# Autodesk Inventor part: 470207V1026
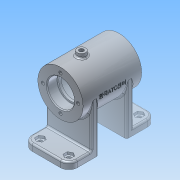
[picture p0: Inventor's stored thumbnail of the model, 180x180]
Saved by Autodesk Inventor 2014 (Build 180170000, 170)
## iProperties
Created: 2017-02
Part Number: 470207V1026
Material: 알루미늄 6061
Document SubType Name: Modeling
Designer: NET
Density: 2.71 g/cm^3
Appearance: 알루미늄 - 평지
Mass: 354.897 g
Surface Area: 425.393 cm^2
Volume: 130.958 cm^3
Author: NET
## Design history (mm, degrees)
sketch "스케치1"
  geometry: L1 (0, 0)-(70, 0); L2 (70, 27)-(70, 17); L3 (0, 17)-(0, 27); L4 (0, 27)-(70, 27); L5 (69, 16)-(58.3, 16); L6 (58, 15.7)-(58, 14); L7 (58, 14)-(55, 14); L8 (55, 14)-(55, 19); L9 (52, 22)-(18, 22); L10 (15, 19)-(15, 14); L11 (15, 14)-(12, 14); L12 (12, 14)-(12, 15.7); L13 (11.7, 16)-(1, 16); L14 (69, 16)-(70, 17); L15 (0, 17)-(1, 16); A1 r 3 centre (18, 19) between (18, 22) and (15, 19); A2 r 3 centre (52, 19) between (55, 19) and (52, 22); A3 r 0.3 centre (11.7, 15.7) between (12, 15.7) and (11.7, 16); A4 r 0.3 centre (58.3, 15.7) between (58.3, 16) and (58, 15.7); 2 further points
  constraints: 30 end point, 8 parallel, 8 point on circle, 8 tangent, 4 centre point, 4 point on line, 3 perpendicular, 2 equal radius, 1 horizontal, 1 vertical alignment
  dimensions: "d0" = 70 distance of L1.end L1.start; "d1" = 54 diameter of L4 L1; "d2" = 3 radius of A1; "d3" = 28 diameter of L7 L1; "d4" = 28 diameter of L11 L1; "d5" = 44 diameter of L9 L1; "d6" = 1 distance of L5.start point (70, 16); "d7" = 1 distance of L2.end point (70, 16) (= d6); "d8" = 1 distance of L3.start point (0, 16) (= d6); "d9" = 1 distance of L13.end point (0, 16) (= d8); "d10" = 12 distance between parallel lines of L12 L3; "d11" = 12 distance between parallel lines of L2 L6; "d12" = 3 distance of L10.end L11.end; "d13" = 3 distance of L6.end L7.end; "d14" = 40 distance between parallel lines of L10 L8; "d15" = 32 diameter of L13 L1; "d16" = 32 diameter of L5 L1; "d17" = 0.3 radius of A3
revolve "회전1" sketch "스케치1" stored, may be unused: angle "d18" = 90 deg
node "작업 평면1"
sketch "스케치2"
  geometry: L1 (70, -27)-(70, 27) reference; L2 (0, -27)-(0, 27) reference; C1 r 5 at (45, 0); 2 further points
  constraints: 1 centre point, 1 horizontal alignment, 1 midpoint
  dimensions: "d20" = 25 distance from line of L1 C1.centre; "d21" = 10 diameter of C1
extrude "돌출1" join sketch "스케치2" stored distance "d22" = 10; taper "d23" = 0 deg
hole "구멍1" diameter "d26" = 5.188; stored, may be unused: countersink angle "d30" = 90 deg, drill point angle "d32" = 118 deg; dims "d27" = 6, "d28" = 4, "d29" = 2, "d31" = 8, "d110" = 10, "d111" = 10
node "작업 평면2"
sketch "스케치3"
  geometry: L1 (0, -27)-(0, 27) reference; L2 (70, -27)-(70, 27) reference; L3 (70, -27)-(70, 27) reference; L4 (0, -27)-(0, 27) reference; L5 (87, 17)-(87, -17); L6 (-17, -17)-(-17, 17); L7 (-17, 27)-(87, -27); L8 (87, 27)-(-17, -27); L9 (0, 27)-(70, 27) reference; L10 (18, -27)-(18, 27); L11 (52, 27)-(52, -27); L12 (77, -27)-(52, -27); L13 (18, -27)-(-7, -27); L14 (-7, 27)-(18, 27); L15 (52, 27)-(77, 27); C1 r 2.5 at (-7, 17); C2 r 2.5 at (77, 17); C3 r 2.5 at (77, -17); C4 r 2.5 at (-7, -17); A1 r 10 centre (77, -17) between (77, -27) and (87, -17); A2 r 10 centre (77, 17) between (87, 17) and (77, 27); A3 r 10 centre (-7, 17) between (-7, 27) and (-17, 17); A4 r 10 centre (-7, -17) between (-17, -17) and (-7, -27); 6 further points; 1 other entity
  constraints: 20 end point, 12 tangent, 8 centre point, 8 point on circle, 6 equal radius, 6 point on line, 5 parallel, 5 perpendicular, 4 coincident, 2 horizontal, 2 midpoint, 1 horizontal alignment, 5 other
  dimensions: "d34" = 104 distance of L7.start L8.start; "d35" = 10 radius of A1; "d36" = 52 distance from line of point (35, -27) L5; "d37" = 17 distance from line of point (35, -27) L11; "d38" = 17 distance from line of point (35, -27) L10; "d39" = 52 distance from line of point (35, -27) L6; "d46" = 5 diameter of C1
extrude "돌출4" join sketch "스케치3" distance "d47" = 8; taper "d48" = 0 deg
sketch "스케치5"
  geometry: L1 (-18, 27)-(-18, -27) reference; L2 (-52, -27)-(-77, -27) reference; L3 (-87, -17)-(-87, 17) reference; L4 (-77, 27)-(-52, 27) reference; L5 (-52, 27)-(-52, -27) reference; L6 (-18, 27)-(7, 27) reference; L7 (17, 17)-(17, -17) reference; L8 (7, -27)-(-18, -27) reference; L9 (-18, -27)-(-18, 27) reference; L10 (-18, 27)-(-10, 27); L11 (-10, 27)-(-10, -27); L12 (-10, -27)-(-18, -27); L13 (-18, -27)-(-18, 27); L14 (-52, 27)-(-60, 27); L15 (-60, 27)-(-60, -27); L16 (-60, -27)-(-52, -27); L17 (-52, -27)-(-52, 27); C1 r 2.5 at (-77, 17) reference; C2 r 2.5 at (-77, -17) reference; C3 r 2.5 at (7, 17) reference; C4 r 2.5 at (7, -17) reference; A1 r 10 centre (-77, -17) between (-87, -17) and (-77, -27) reference; A2 r 10 centre (-77, 17) between (-77, 27) and (-87, 17) reference; A3 r 10 centre (7, 17) between (17, 17) and (7, 27) reference; A4 r 10 centre (7, -17) between (7, -27) and (17, -17) reference; 1 further point
  constraints: 16 end point, 4 parallel, 2 horizontal, 2 perpendicular, 2 point on line
  dimensions: "d49" = 8 distance of L11.end L12.end; "d50" = 8 distance of L15.end L16.end
extrude "돌출5" join sketch "스케치5" stored distance "d51" = 8; taper "d52" = 0 deg
sketch "스케치6"
  geometry: L1 (-10, 27)-(-10, -27) reference; L2 (7, -27)-(-10, -27) reference; L3 (17, 17)-(17, -17) reference; L4 (-10, 27)-(7, 27) reference; L5 (-18, 27)-(-10, 27) reference; L6 (-18, -27)-(-18, 27) reference; L7 (-10, -27)-(-18, -27) reference; L8 (-60, -27)-(-60, 27) reference; L9 (-77, 27)-(-60, 27) reference; L10 (-87, -17)-(-87, 17) reference; L11 (-60, -27)-(-77, -27) reference; L12 (-52, -27)-(-60, -27) reference; L13 (-52, 27)-(-52, -27) reference; L14 (-60, 27)-(-52, 27) reference; L15 (-74.402, 21.5)-(-71.804, 17); L16 (-71.804, 17)-(-74.402, 12.5); L17 (-74.402, 12.5)-(-79.598, 12.5); L18 (-79.598, 12.5)-(-82.196, 17); L19 (-82.196, 17)-(-79.598, 21.5); L20 (-79.598, 21.5)-(-74.402, 21.5); L21 (-74.402, -12.5)-(-71.804, -17); L22 (-71.804, -17)-(-74.402, -21.5); L23 (-74.402, -21.5)-(-79.598, -21.5); L24 (-79.598, -21.5)-(-82.196, -17); L25 (-82.196, -17)-(-79.598, -12.5); L26 (-79.598, -12.5)-(-74.402, -12.5); L27 (9.598, -12.5)-(12.196, -17); L28 (12.196, -17)-(9.598, -21.5); L29 (9.598, -21.5)-(4.402, -21.5); L30 (4.402, -21.5)-(1.804, -17); L31 (1.804, -17)-(4.402, -12.5); L32 (4.402, -12.5)-(9.598, -12.5); L33 (9.598, 21.5)-(12.196, 17); L34 (12.196, 17)-(9.598, 12.5); L35 (9.598, 12.5)-(4.402, 12.5); L36 (4.402, 12.5)-(1.804, 17); L37 (1.804, 17)-(4.402, 21.5); L38 (4.402, 21.5)-(9.598, 21.5); C1 r 2.5 at (7, 17) reference; C2 r 2.5 at (7, -17) reference; C3 r 2.5 at (7, 17) reference; C4 r 2.5 at (7, -17) reference; C5 r 2.5 at (-77, 17) reference; C6 r 2.5 at (-77, -17) reference; A1 r 10 centre (7, -17) between (7, -27) and (17, -17) reference; A2 r 10 centre (7, 17) between (17, 17) and (7, 27) reference; A3 r 10 centre (-77, 17) between (-77, 27) and (-87, 17) reference; A4 r 10 centre (-77, -17) between (-87, -17) and (-77, -27) reference; 5 further points
  constraints: 48 end point, 4 coincident, 4 parallel, 3 equal length, 52 other
  dimensions: "d53" = 9 distance between parallel lines of L20 L17
extrude "돌출6" cut sketch "스케치6" distance "d54" = 3; taper "d55" = 0 deg
node "작업 평면3"
sketch "스케치7"
  geometry: L1 (35, 27)-(-35, 27) reference; L2 (-35, 27)-(-35, -27) reference; L3 (35, 27)-(35, -27) reference; 2 further points
  constraints: 1 other
  dimensions: "d56" = 35 distance from line of L2 point (0, 0); "d57" = 27 distance from line of L1 point (0, 0)
feature "엠보싱1" sketch "스케치7" dims "d0" = 70, "d1" = 54, "d2" = 3, "d3" = 28, "d4" = 28, "d5" = 44, "d6" = 1, "d7" = 1 (= d6), "d8" = 1 (= d6), "d9" = 1 (= d8), "d10" = 12, "d11" = 12, "d12" = 3, "d13" = 3, "d14" = 40, "d15" = 32, "d16" = 32, "d17" = 0.3, "d58" = 0.5, "d59" = 0
sketch "스케치8"
  geometry: C1 r 27 at (0, 0) reference; A1 r 21 centre (0, 0) between (0, 21) and (21, 0); 2 further points
  constraints: 4 point on circle, 1 centre point, 1 coincident
  dimensions: "d60" = 42 diameter of A1
hole "구멍2" sketch "스케치8" at (0, 21), (21, 0), (0, -21), (-21, 0) diameter "d61" = 4; stored, may be unused: countersink angle "d65" = 90 deg, drill point angle "d67" = 118 deg; dims "d62" = 6, "d63" = 4, "d64" = 2, "d66" = 10
sketch "스케치9"
  geometry: C1 r 17 at (0, 0) reference; A1 r 21 centre (0, 0) between (0, 21) and (21, 0); 2 further points
  constraints: 4 point on circle, 1 centre point, 1 coincident
  dimensions: "d68" = 42 diameter of A1
hole "구멍3" sketch "스케치9" at (0, 21), (21, 0), (0, -21), (-21, 0) diameter "d69" = 4; stored, may be unused: countersink angle "d73" = 90 deg, drill point angle "d75" = 118 deg; dims "d70" = 6, "d71" = 4, "d72" = 2, "d74" = 10
feature "스레드1" dims "d76" = 8, "d77" = 0
feature "스레드2" dims "d78" = 8, "d79" = 0
feature "스레드3" dims "d80" = 8, "d81" = 0
feature "스레드4" dims "d82" = 8, "d83" = 0
feature "스레드5" dims "d84" = 8, "d85" = 0
feature "스레드6" dims "d86" = 8, "d87" = 0
feature "스레드7" dims "d88" = 8, "d89" = 0
feature "스레드8" dims "d90" = 8, "d91" = 0
node "작업 평면4"
sketch "스케치10"
  geometry: L1 (-27.431, 1.941)-(-26.933, 1.906) reference; L2 (-26.954, 1.576)-(-27.453, 1.605) reference; L3 (0, 0)-(0, -30); L4 (0, 0)-(16.339, -25.16); C1 r 22 at (0, 0) reference; A1 r 27.5 centre (0, 0) between (-27.431, 1.941) and (-27.453, 1.605) reference; A2 r 27 centre (0, 0) between (-26.954, 1.576) and (-26.933, 1.906) reference; 1 further point
  constraints: 4 end point, 1 vertical
  dimensions: "d94" = 30 distance of L3.start L3.end; "d96" = 30 distance of L3.start L4.end; "d97" = 33 deg angle of L3 L4
  node "절단 모서리 투영4"
node "작업 평면5"
sketch "스케치11"
  geometry: C1 r 6 at (0, 0); 4 further points
  constraints: 1 centre point, 1 coincident
  dimensions: "d98" = 12 diameter of C1
extrude "돌출7" join sketch "스케치11" stored distance "d99" = 3; taper "d100" = 0 deg
hole "구멍4" diameter "d103" = 5.188; stored, may be unused: countersink angle "d107" = 90 deg, drill point angle "d109" = 118 deg; dims "d101" = 10, "d102" = 10, "d104" = 6, "d105" = 4, "d106" = 2, "d108" = 10
fillet "모깎기1" dims "d112" = 2
node "솔리드1"
node "투영된 루프1"
node "투영된 루프2"
node "절단 모서리 투영2"
node "절단 모서리 투영3"
other parameters: "d19" = 32
